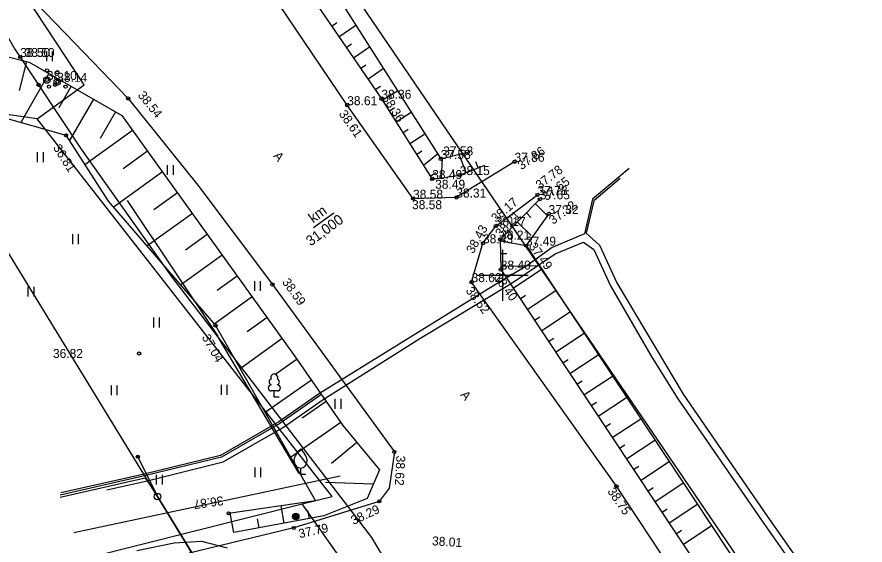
# Model space of a CAD drawing. Extents: x 627548 to 628052, y 6467984 to 6468802.
# Drawn here: x 627662.1 to 627728.3, y 6468629 to 6468670.2 of the extents above; entities that cross this region are included whole.
import ezdxf

# ---------------------------------------------------------------- set-up
doc = ezdxf.new("R2010")
doc.units = 0
for name, color, linetype in [('HALJASTUS', 7, 'Continuous'), ('KORGUS-EH2000', 7, 'Continuous'), ('KPKAABEL', 7, 'Continuous'), ('MOOTKORG-EH2000', 7, 'Continuous'), ('MOOTMPUNKT', 7, 'Continuous'), ('MPKAABEL', 7, 'Continuous'), ('MPOHULIIN', 7, 'Continuous'), ('PIIR', 7, 'Continuous'), ('POST', 7, 'Continuous'), ('PUU', 7, 'Continuous'), ('RAJATIS', 7, 'Continuous'), ('RELJEEF', 7, 'Continuous'), ('SIOHULIIN', 7, 'Continuous'), ('SITRASS', 7, 'Continuous'), ('TEE', 7, 'Continuous'), ('VORK', 7, 'Continuous')]:
    doc.layers.add(name, color=color, linetype=linetype)

msp = doc.modelspace()

# ---------------------------------------------------------------- linework, layer by layer
at = {"layer": 'HALJASTUS'}
for p, q in [((627664.377, 6468667.467), (627664.377, 6468666.706)), ((627664.832, 6468667.467), (627664.832, 6468666.706)), ((627663.661, 6468659.603), (627663.661, 6468658.842)), ((627664.116, 6468659.603), (627664.116, 6468658.842)), ((627673.818, 6468658.59), (627673.818, 6468657.829)), ((627674.273, 6468658.59), (627674.273, 6468657.829)), ((627666.412, 6468653.202), (627666.412, 6468652.441)), ((627666.867, 6468653.202), (627666.867, 6468652.441)), ((627662.937, 6468649.105), (627662.937, 6468648.343)), ((627663.393, 6468649.105), (627663.393, 6468648.343)), ((627680.619, 6468649.545), (627680.619, 6468648.784)), ((627681.074, 6468649.545), (627681.074, 6468648.784)), ((627672.736, 6468646.699), (627672.736, 6468645.938)), ((627673.191, 6468646.699), (627673.191, 6468645.938)), ((627669.43, 6468641.403), (627669.43, 6468640.642)), ((627669.885, 6468641.403), (627669.885, 6468640.642)), ((627678.026, 6468641.446), (627678.026, 6468640.685)), ((627678.481, 6468641.446), (627678.481, 6468640.685)), ((627686.909, 6468640.354), (627686.909, 6468639.593)), ((627687.364, 6468640.354), (627687.364, 6468639.593)), ((627680.647, 6468635.002), (627680.647, 6468634.24)), ((627681.102, 6468635.002), (627681.102, 6468634.24)), ((627672.954, 6468634.443), (627672.954, 6468633.682)), ((627673.409, 6468634.443), (627673.409, 6468633.682))]:
    msp.add_line(p, q, dxfattribs=at)
for points in [[(627684.123, 6468634.54), (627677.852, 6468645.107)], [(627687.331, 6468634.332), (627666.528, 6468629.909)]]:
    msp.add_lwpolyline(points, dxfattribs=at)
at = {"layer": 'KORGUS-EH2000'}
for centre in [(627670.77, 6468663.797), (627665.91, 6468660.927), (627682.03, 6468649.277), (627677.58, 6468646.087), (627671.62, 6468643.897), (627691.556, 6468636.216), (627708.91, 6468633.537), (627690.377, 6468632.362), (627678.61, 6468631.427), (627683.705, 6468630.285)]:
    msp.add_circle(centre, 0.125, dxfattribs=at)
at = {"layer": 'KPKAABEL'}
for points in [[(627669.097, 6468633.249), (627672.145, 6468633.949), (627678.191, 6468635.434), (627682.816, 6468638.102), (627686, 6468640.309), (627693.531, 6468645.059), (627700.672, 6468649.352), (627704.105, 6468651.68), (627706.332, 6468652.594), (627707.141, 6468652.008), (627708.445, 6468649.168), (627711.578, 6468643.754), (627713.652, 6468640.441), (627720.223, 6468630.902), (627727.156, 6468621.02)], [(627685.782, 6468640.643), (627682.599, 6468638.441), (627678.043, 6468635.809), (627672.046, 6468634.344), (627665.462, 6468632.852)], [(627665.442, 6468632.693), (627672.08, 6468634.198), (627673.058, 6468632.736)]]:
    msp.add_lwpolyline(points, dxfattribs=at)
at = {"layer": 'MOOTMPUNKT'}
for centre in [(627662.329, 6468667.035), (627664.416, 6468665.237), (627665.228, 6468665.1), (627690.541, 6468663.778), (627687.872, 6468663.274), (627695.175, 6468659.082), (627700.939, 6468658.86), (627694.507, 6468657.515), (627696.664, 6468657.822), (627696.392, 6468656.072), (627702.732, 6468656.268), (627693.013, 6468655.978), (627702.917, 6468655.933), (627703.599, 6468654.781), (627699.472, 6468653.844), (627699.818, 6468652.789), (627698.476, 6468652.499), (627701.838, 6468652.316), (627699.865, 6468650.447), (627697.582, 6468649.469)]:
    msp.add_circle(centre, 0.125, dxfattribs=at)
at = {"layer": 'MPKAABEL'}
for points in [[(627709.89, 6468658.325), (627707.021, 6468655.937), (627706.401, 6468653.245), (627703.889, 6468652.183), (627701.892, 6468650.742), (627699.254, 6468649.165), (627685.699, 6468640.768), (627682.519, 6468638.568), (627677.987, 6468635.95), (627672.012, 6468634.49), (627665.508, 6468633.016)], [(627709.197, 6468657.565), (627707.121, 6468655.82), (627706.531, 6468653.289), (627707.578, 6468652.359), (627708.93, 6468649.422), (627714.121, 6468640.738), (627720.672, 6468631.211), (627727.602, 6468621.34), (627730.988, 6468616.672), (627738.102, 6468605.93), (627740.809, 6468601.93), (627752.031, 6468586.762), (627759.828, 6468575.75), (627762.551, 6468571.488), (627768.93, 6468563.398), (627770.031, 6468560.512), (627770.43, 6468560.219), (627773.398, 6468559.539), (627777.801, 6468552.941), (627777.828, 6468552.219), (627775.031, 6468546.871), (627775.602, 6468546.309)]]:
    msp.add_lwpolyline(points, dxfattribs=at)
at = {"layer": 'MPOHULIIN'}
for points in [[(627673.058, 6468632.736), (627650.185, 6468670.056)], [(627679.915, 6468621.5), (627673.058, 6468632.736), (627672.71, 6468633.307)]]:
    msp.add_lwpolyline(points, dxfattribs=at)
at = {"layer": 'PIIR'}
for p, q in [((627666.22, 6468704.47), (627739.66, 6468596.76)), ((627667.34, 6468664.86), (627649.05, 6468692.73)), ((627663.66, 6468662.2), (627667.34, 6468664.86)), ((627663.66, 6468662.2), (627654.85, 6468663.52)), ((627686.69, 6468632.75), (627663.66, 6468662.2)), ((627684.35, 6468632.16), (627686.69, 6468632.75)), ((627667.6, 6468627.959), (627684.35, 6468632.16)), ((627688.18, 6468626.77), (627684.35, 6468632.16))]:
    msp.add_line(p, q, dxfattribs=at)
at = {"layer": 'POST'}
msp.add_lwpolyline([(627671.521, 6468635.845), (627673.058, 6468632.736)], dxfattribs=at)
for centre, radius in [((627671.521, 6468635.845), 0.125), ((627671.521, 6468635.845), 0.117), ((627671.521, 6468635.845), 0.109), ((627671.521, 6468635.845), 0.102), ((627671.521, 6468635.845), 0.0938), ((627671.521, 6468635.845), 0.086), ((627671.521, 6468635.845), 0.0782), ((627671.521, 6468635.845), 0.0704), ((627671.521, 6468635.845), 0.0626), ((627671.521, 6468635.845), 0.0548), ((627671.521, 6468635.845), 0.047), ((627671.521, 6468635.845), 0.0392), ((627671.521, 6468635.845), 0.0314), ((627671.521, 6468635.845), 0.0236), ((627671.521, 6468635.845), 0.0158), ((627671.521, 6468635.845), 0.00798), ((627671.521, 6468635.845), 0.000186), ((627673.058, 6468632.736), 0.25)]:
    msp.add_circle(centre, radius, dxfattribs=at)
at = {"layer": 'PUU'}
for p, q in [((627682.416, 6468640.979), (627681.936, 6468640.979)), ((627682.176, 6468640.504), (627682.176, 6468640.979)), ((627682.556, 6468640.504), (627682.176, 6468640.504)), ((627684.239, 6468634.462), (627684.239, 6468634.962)), ((627684.639, 6468634.462), (627684.239, 6468634.462))]:
    msp.add_line(p, q, dxfattribs=at)
for points in [[(627677.786, 6468645.253), (627670.724, 6468655.836)], [(627683.739, 6468635.462), (627683.739, 6468635.612), (627683.749, 6468635.677), (627683.784, 6468635.807), (627683.844, 6468635.927), (627683.989, 6468636.162), (627684.149, 6468636.367), (627684.239, 6468636.462)], [(627684.739, 6468635.462), (627684.739, 6468635.612), (627684.729, 6468635.677), (627684.694, 6468635.807), (627684.634, 6468635.927), (627684.489, 6468636.162), (627684.329, 6468636.367), (627684.239, 6468636.462)]]:
    msp.add_lwpolyline(points, dxfattribs=at)
for centre, radius in [((627664.416, 6468665.237), 0.25), ((627664.416, 6468665.987), 0.125), ((627665.228, 6468665.85), 0.125), ((627663.766, 6468664.862), 0.125), ((627664.578, 6468664.725), 0.125), ((627665.066, 6468664.862), 0.125), ((627665.228, 6468665.1), 0.25), ((627665.878, 6468664.725), 0.125)]:
    msp.add_circle(centre, radius, dxfattribs=at)
for centre, radius, start, end in [((627682.176, 6468642.024), 0.277, 332.5799, 207.4201), ((627682.006, 6468641.677), 0.233, 109.02174, 253.14154), ((627682.346, 6468641.677), 0.233, 286.85082, 70.98591), ((627681.938, 6468641.217), 0.238, 90.0016, 269.3953), ((627682.413, 6468641.217), 0.238, 270.6047, 89.9984), ((627684.239, 6468635.462), 0.5, 180, 0)]:
    msp.add_arc(centre, radius, start, end, dxfattribs=at)
at = {"layer": 'RAJATIS'}
for radius in [0.25, 0.225, 0.2, 0.175, 0.15, 0.125, 0.1, 0.075, 0.05, 0.025]:
    msp.add_circle((627683.853, 6468631.183), radius, dxfattribs=at)
at = {"layer": 'RELJEEF'}
for p, q in [((627686.66, 6468669.438), (627687.072, 6468669.721)), ((627687.226, 6468668.613), (627688.544, 6468669.517)), ((627687.791, 6468667.789), (627688.203, 6468668.071)), ((627688.357, 6468666.964), (627689.617, 6468667.828)), ((627662.823, 6468666.694), (627662.25, 6468664.41)), ((627688.922, 6468666.139), (627689.334, 6468666.422)), ((627689.488, 6468665.314), (627690.691, 6468666.139)), ((627664.578, 6468665.749), (627662.38, 6468661.927)), ((627666.312, 6468664.752), (627665.338, 6468663.059)), ((627690.053, 6468664.49), (627690.465, 6468664.772)), ((627690.614, 6468663.662), (627691.791, 6468664.407)), ((627668.046, 6468663.755), (627666.178, 6468660.508)), ((627691.149, 6468662.817), (627691.572, 6468663.085)), ((627669.779, 6468662.758), (627668.585, 6468660.682)), ((627691.684, 6468661.972), (627692.864, 6468662.719)), ((627671.107, 6468661.311), (627667.377, 6468658.628)), ((627692.219, 6468661.128), (627692.642, 6468661.395)), ((627692.754, 6468660.283), (627693.936, 6468661.031)), ((627672.275, 6468659.688), (627670.365, 6468658.313)), ((627693.289, 6468659.438), (627693.712, 6468659.705)), ((627693.824, 6468658.593), (627694.916, 6468659.489)), ((627695.224, 6468657.617), (627695.304, 6468659.114)), ((627697.172, 6468658.02), (627696.626, 6468659.418)), ((627698.103, 6468658.384), (627697.922, 6468658.85)), ((627696.214, 6468657.758), (627696.143, 6468658.253)), ((627673.443, 6468658.064), (627669.606, 6468655.304)), ((627694.359, 6468657.748), (627694.782, 6468658.016)), ((627674.611, 6468656.44), (627672.765, 6468655.113)), ((627702.566, 6468655.577), (627703.46, 6468654.696)), ((627675.779, 6468654.817), (627672.233, 6468652.266)), ((627701.864, 6468654.865), (627702.22, 6468654.514)), ((627701.162, 6468654.153), (627702.23, 6468653.1)), ((627676.947, 6468653.193), (627675.247, 6468651.97)), ((627700.46, 6468653.44), (627700.816, 6468653.089)), ((627699.82, 6468652.704), (627701.838, 6468652.316)), ((627678.114, 6468651.57), (627674.86, 6468649.229)), ((627699.84, 6468651.704), (627700.34, 6468651.714)), ((627699.86, 6468650.704), (627702.867, 6468650.764)), ((627700.829, 6468648.995), (627703.058, 6468650.476)), ((627679.282, 6468649.946), (627677.728, 6468648.828)), ((627700.276, 6468649.828), (627700.693, 6468650.105)), ((627680.45, 6468648.322), (627677.488, 6468646.191)), ((627701.383, 6468648.162), (627701.799, 6468648.439)), ((627701.936, 6468647.329), (627704.163, 6468648.809)), ((627703.043, 6468645.663), (627705.269, 6468647.142)), ((627681.618, 6468646.699), (627680.062, 6468645.58)), ((627702.489, 6468646.496), (627702.906, 6468646.773)), ((627682.786, 6468645.075), (627679.503, 6468642.714)), ((627703.596, 6468644.83), (627704.013, 6468645.107)), ((627704.149, 6468643.997), (627706.374, 6468645.475)), ((627705.256, 6468642.332), (627707.479, 6468643.808)), ((627683.951, 6468643.449), (627682.207, 6468642.239)), ((627704.703, 6468643.165), (627705.119, 6468643.441)), ((627685.091, 6468641.807), (627681.459, 6468639.284)), ((627705.81, 6468641.499), (627706.226, 6468641.775)), ((627706.363, 6468640.666), (627708.585, 6468642.142)), ((627707.47, 6468639), (627709.69, 6468640.475)), ((627686.232, 6468640.164), (627684.343, 6468638.852)), ((627706.916, 6468639.833), (627707.333, 6468640.109)), ((627687.373, 6468638.521), (627683.448, 6468635.795)), ((627708.023, 6468638.167), (627708.439, 6468638.443)), ((627708.576, 6468637.334), (627710.795, 6468638.808)), ((627709.683, 6468635.668), (627711.9, 6468637.141)), ((627688.625, 6468636.963), (627686.636, 6468635.327)), ((627709.13, 6468636.501), (627709.546, 6468636.778)), ((627710.236, 6468634.835), (627710.653, 6468635.112)), ((627710.79, 6468634.002), (627713.006, 6468635.474)), ((627689.909, 6468633.691), (627686.167, 6468633.836)), ((627711.896, 6468632.336), (627714.111, 6468633.807)), ((627711.343, 6468633.169), (627711.759, 6468633.446)), ((627682.954, 6468630.657), (627682.703, 6468632.011)), ((627712.45, 6468631.503), (627712.866, 6468631.78)), ((627713.003, 6468630.67), (627715.216, 6468632.14)), ((627679.021, 6468629.928), (627678.74, 6468631.445)), ((627684.921, 6468631.021), (627684.803, 6468631.657)), ((627680.988, 6468630.292), (627680.855, 6468631.01)), ((627714.11, 6468629.004), (627716.321, 6468630.474)), ((627713.556, 6468629.837), (627713.973, 6468630.114))]:
    msp.add_line(p, q, dxfattribs=at)
for points in [[(627624.669, 6468783.336), (627635.143, 6468764.467), (627644.826, 6468744.62), (627663.453, 6468714.069), (627667.771, 6468700.282), (627669.788, 6468697.789), (627680.393, 6468682.345), (627695.175, 6468659.082), (627697.462, 6468659.655)], [(627621.271, 6468781.45), (627631.48, 6468762.833), (627641.678, 6468741.628), (627656.496, 6468717.027), (627668.985, 6468695.815), (627678.436, 6468681.433), (627690.541, 6468663.778), (627694.507, 6468657.515), (627696.664, 6468657.822), (627698.617, 6468658.584)], [(627630.555, 6468702.745), (627633.602, 6468703.792), (627636.779, 6468703.755), (627641.143, 6468701.858), (627642.594, 6468699.898), (627643.694, 6468698.663), (627646.012, 6468695.356), (627648.98, 6468689.647), (627650.921, 6468685.967), (627652.256, 6468681.471), (627652.071, 6468675.492), (627653.291, 6468671.992), (627655.882, 6468668.896), (627659.102, 6468667.627), (627663.024, 6468666.643), (627670.269, 6468662.476), (627683.816, 6468643.643), (627687.532, 6468638.292), (627690.387, 6468634.82), (627689.443, 6468632.589), (627686.057, 6468631.231), (627679.021, 6468629.928)], [(627647.397, 6468683.918), (627648.135, 6468683.852), (627648.322, 6468680.758), (627647.557, 6468678.266), (627648.942, 6468673.349), (627651.927, 6468666.4), (627655.621, 6468663.838), (627665.909, 6468660.929), (627669.195, 6468655.778), (627677.582, 6468646.082), (627685.387, 6468632.394), (627678.61, 6468631.426)], [(627702.917, 6468655.933), (627699.818, 6468652.789), (627699.865, 6468650.447), (627717.165, 6468624.405), (627735.281, 6468598.508), (627755.388, 6468570.758), (627765.753, 6468554.048), (627767.397, 6468553.344), (627769.66, 6468554.263)], [(627703.599, 6468654.781), (627701.838, 6468652.316), (627719.945, 6468625.009), (627738.054, 6468601.247), (627758.412, 6468571.035), (627762.457, 6468563.483), (627767.072, 6468554.502), (627769.302, 6468555.394)]]:
    msp.add_lwpolyline(points, dxfattribs=at)
at = {"layer": 'SIOHULIIN'}
msp.add_lwpolyline([(627673.058, 6468632.736), (627701.778, 6468585.756)], dxfattribs=at)
at = {"layer": 'SITRASS'}
for points in [[(627601.95, 6468775.665), (627611.516, 6468756.586), (627616.834, 6468745.298), (627619.184, 6468741.186), (627623.567, 6468733.678), (627630.719, 6468721.267), (627637.953, 6468708.68), (627647.64, 6468692.032), (627654.507, 6468680.481), (627661.905, 6468667.643), (627667.084, 6468659.838), (627674.129, 6468649.944), (627689.767, 6468629.543), (627695.628, 6468619.665), (627699.564, 6468614.681), (627710.374, 6468599.048), (627720.659, 6468583.91), (627729.18, 6468571.423), (627736.574, 6468559.697), (627746.582, 6468544.707), (627757.269, 6468529.067), (627768.1, 6468513.354)], [(627671.445, 6468628.538), (627674.365, 6468629.128), (627676.49, 6468629.264), (627678.485, 6468628.725)]]:
    msp.add_lwpolyline(points, dxfattribs=at)
at = {"layer": 'TEE'}
msp.add_line((627685.242, 6468653.735), (627686.816, 6468654.883), dxfattribs=at)
for points in [[(627700.939, 6468658.86), (627696.392, 6468656.072), (627693.013, 6468655.978), (627687.872, 6468663.274), (627673.734, 6468684.205), (627667.271, 6468695.423), (627655.655, 6468715.038), (627640.744, 6468741.218), (627629.668, 6468761.293)], [(627642.851, 6468701.697), (627643.652, 6468701.039), (627643.972, 6468700.891), (627645.246, 6468699.098), (627649.286, 6468692.707), (627654.27, 6468685.483), (627656.176, 6468682.398), (627657.145, 6468678.821), (627659.852, 6468674.505), (627663.528, 6468671.281), (627666.594, 6468668.111), (627670.77, 6468663.802), (627676.196, 6468657.041), (627682.033, 6468649.275), (627691.556, 6468636.216), (627691.146, 6468633.38), (627690.377, 6468632.362), (627683.705, 6468630.285), (627675.534, 6468628.326)], [(627770.953, 6468554.632), (627768.554, 6468552.919), (627764.495, 6468553.409), (627737.106, 6468593.181), (627733.836, 6468597.706), (627715.765, 6468623.144), (627708.906, 6468633.534), (627697.582, 6468649.469), (627698.476, 6468652.499), (627699.472, 6468653.844), (627702.732, 6468656.268)]]:
    msp.add_lwpolyline(points, dxfattribs=at)
at = {"layer": 'VORK'}
for p, q in [((627700, 6468652), (627700, 6468648)), ((627698, 6468650), (627702, 6468650))]:
    msp.add_line(p, q, dxfattribs=at)

# ---------------------------------------------------------------- texts
at = {"layer": 'KORGUS-EH2000'}
for s, p in [('38.50', (627662.679, 6468667.035)), ('37.58', (627695.369, 6468659.353)), ('38.49', (627694.74, 6468656.756)), ('38.58', (627692.935, 6468655.161)), (' 36.82', (627664.632, 6468643.55))]:
    msp.add_text(s, height=0.7, dxfattribs=at).set_placement(p)
for s, rotation, p in [(' 38.54', 308.74858, (627671.316, 6468664.24)), ('38.36', 302.19909, (627690.568, 6468663.851)), ('38.61', 305.35014, (627687.187, 6468662.589)), (' 36.81', 302.5352, (627664.729, 6468660.176)), ('37.86', 34.98199, (627701.481, 6468658.196)), ('37.78', 37.53197, (627702.922, 6468656.674)), ('37.65', 36.44357, (627703.44, 6468655.786)), ('38.17', 40.54641, (627699.487, 6468654.078)), ('37.32', 36.22289, (627703.951, 6468653.936)), ('38.21', 46.49266, (627699.858, 6468652.914)), ('38.43', 60.57664, (627697.717, 6468651.641)), ('37.49', 306.03159, (627702.015, 6468652.245)), (' 38.59', 305.65862, (627682.602, 6468649.683)), ('38.40', 305.82943, (627699.287, 6468649.82)), ('38.62', 307.06894, (627697.091, 6468648.789)), (' 37.04', 299.69211, (627676.366, 6468645.389)), (' 38.62', 266.87394, (627691.731, 6468636.207)), (' 38.75', 304.94711, (627708.011, 6468633.355)), (' 36.87', 188.12892, (627678.412, 6468632.812)), (' 38.29', 25.00888, (627688.122, 6468630.401)), (' 37.79', 12.02827, (627683.9, 6468629.432)), (' 38.01', 356.40462, (627694.223, 6468628.954))]:
    msp.add_text(s, height=0.7, rotation=rotation, dxfattribs=at).set_placement(p)
at = {"layer": 'MOOTKORG-EH2000'}
for s, p in [('38.50', (627662.329, 6468667.035)), ('38.10', (627664.416, 6468665.237)), ('38.14', (627665.228, 6468665.1)), ('38.36', (627690.541, 6468663.778)), ('38.61', (627687.872, 6468663.274)), ('37.58', (627695.175, 6468659.082)), ('37.86', (627700.939, 6468658.86)), ('38.49', (627694.507, 6468657.515)), ('38.15', (627696.664, 6468657.822)), ('37.78', (627702.732, 6468656.268)), ('38.58', (627693.013, 6468655.978)), ('38.31', (627696.392, 6468656.072)), ('37.65', (627702.917, 6468655.933)), ('37.32', (627703.599, 6468654.781)), ('38.17', (627699.472, 6468653.844)), ('38.43', (627698.476, 6468652.499)), ('38.21', (627699.818, 6468652.789)), ('37.49', (627701.838, 6468652.316)), ('38.40', (627699.865, 6468650.447)), ('38.62', (627697.582, 6468649.469))]:
    msp.add_text(s, height=0.7, dxfattribs=at).set_placement(p)
at = {"layer": 'TEE'}
for s, height, rotation, p in [('A', 0.7, 309.2277, (627682.064, 6468659.299)), ('km', 0.8, 36.11782, (627685.21, 6468654.041)), ('31,000', 0.8, 36.11782, (627685.011, 6468652.246)), ('A', 0.7, 308.61105, (627696.677, 6468640.661))]:
    msp.add_text(s, height=height, rotation=rotation, dxfattribs=at).set_placement(p)

doc.saveas('drawing.dxf')
